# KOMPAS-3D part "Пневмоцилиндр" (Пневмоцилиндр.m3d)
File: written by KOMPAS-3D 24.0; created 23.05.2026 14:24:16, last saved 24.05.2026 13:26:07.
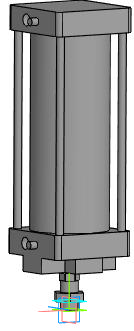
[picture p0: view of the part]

Document properties: Автор: R2D2; Полное имя файла: E:\Работа\Зайцев\GVKR1331E-1W-Fb-2P Задвижка шиберная DN.ru Ду50-300 Ру16-10-6\исходные материалы\DN300\Пневмоцилиндр.m3d

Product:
- Part/product: Пневмоцилиндр
    Масса: 96.248058

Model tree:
1. Эскиз:1
2. Элемент выдавливания:1
3. Смещенная плоскость:1
4. Эскиз:2
5. Элемент выдавливания:2
6. Эскиз:3  (with: Грань.Элемент выдавливания:1)
7. Элемент выдавливания:3
8. Эскиз:4  (with: Грань.Элемент выдавливания:3)
9. Элемент выдавливания:4  (with: Грань.Элемент выдавливания:3)
     Расстояние 2 = 15; Смещение 2 = 5
10. Эскиз:5  (with: Грань.Элемент выдавливания:3)
11. Элемент выдавливания:5
12. Эскиз:6  (with: Грань.Элемент выдавливания:5)
13. Элемент выдавливания:6
14. Эскиз:7  (with: Грань.Элемент выдавливания:6)
15. Элемент выдавливания:7
16. Эскиз:8  (with: Грань.Элемент выдавливания:7, Ребро.Элемент выдавливания:6)
17. Элемент выдавливания:8
18. Эскиз:9  (with: Грань.Элемент выдавливания:6, Вершина.Элемент выдавливания:8)
19. Элемент выдавливания:9  (with: Грань.Элемент выдавливания:8)
     Расстояние 1 = 401
20. Массив по концентрической сетке:1  (with: Элемент выдавливания:9, Эскиз:9)  (4 pattern instances)
     Шаг 2 = 360
21. Скругление:1  (with: Ребро.Элемент выдавливания:6, Ребро.Элемент выдавливания:8)
     Радиус = 10
22. Эскиз:10  (with: Грань.Элемент выдавливания:5, Ребро.Элемент выдавливания:6, Ребро.Элемент выдавливания:8)
23. Элемент выдавливания:10
24. Эскиз:11  (with: Грань.Элемент выдавливания:5, Ребро.Элемент выдавливания:10)
25. Элемент выдавливания:11
26. Эскиз:12  (with: Ребро.Элемент выдавливания:6, Ребро.Элемент выдавливания:5)
27. Элемент выдавливания:12

Expressions: k/2; c-2*g+x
